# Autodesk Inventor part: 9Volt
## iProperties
Shininess: 64.0
Length Units: 11272
Angle Units: 11279
Time Units: 11290
Mass Units: 11286
Length Display Precision: 3
Angle Display Precision: 2
Compacted: True
Part Number: 9Volt
Document SubType Name: Modeling
Created: 2002-11
Designer: Ron Crain
Catalog Web Link: http://www.arken.net
Density: 0.0
Volumn: 0.0
Area: 0.0
PropertySet Name: Model Information
Control State: 0
Master: False
Checked Out: False
Author: Ron Crain
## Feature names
1. Extrusion1
2. Fillet1
3. Extrusion2
4. Fillet2
5. Revolution1
6. Sweep1
